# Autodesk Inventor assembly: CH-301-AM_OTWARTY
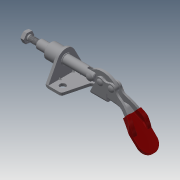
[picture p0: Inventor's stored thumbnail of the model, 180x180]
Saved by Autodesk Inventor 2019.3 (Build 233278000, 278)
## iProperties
Company: Î¢ÈíÖÐ¹ú
Created: 2012-09
Part Number: CH-301-AM_OTWARTY
Material: Ogólny
Description: STEP AP203
Document SubType Name: Assembly
Designer: CADENGINEERING4
Sending System: SolidWorks 2010
Preprocessor: SwSTEP 2.0
Title: CH-301-AM.STEP
Author: Î¢ÈíÓÃ»§
Revision Number: ÈÎºÎ
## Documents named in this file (10)
- D:\Vault_2016\Projekty\STRONA\Push-pull clamp\CH-301-AM\CH-301-AM_OTWARTY.iam
- D:\Vault_2016\Projekty\STRONA\Push-pull clamp\CH-301-AM\CH-SA-042007 SPINDLE SUPPLIED.ipt
- D:\Vault_2016\Projekty\STRONA\Push-pull clamp\CH-301-AM\CH-301-AM-02 CREST STALK.ipt
- D:\Vault_2016\Projekty\STRONA\Push-pull clamp\CH-301-AM\CH-301-AM-05 LEAD SET.ipt
- D:\Vault_2016\Projekty\STRONA\Push-pull clamp\CH-301-AM\CH-301-06.ipt
- D:\Vault_2016\Projekty\STRONA\Push-pull clamp\CH-301-AM\CH-301-AM-03 HANDLE.iam
- D:\Vault_2016\Projekty\STRONA\Push-pull clamp\CH-301-AM\CH-301-07.ipt
- D:\Vault_2016\Projekty\STRONA\Push-pull clamp\CH-301-AM\M4 Nut.ipt
- D:\Vault_2016\Projekty\STRONA\Push-pull clamp\CH-301-AM\CH-301-AM-04 CONNECTING-PLATE.ipt
- D:\Vault_2016\Projekty\STRONA\Push-pull clamp\CH-301-AM\CH-301-AM-01 BASE.ipt
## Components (10 placed, 10 different names)
1. CH-SA-042007 SPINDLE SUPPLIED_1 — Zestawiające:1, Zestawiające:2, Zestawiające:4
2. CH-301-AM-02 CREST STALK_2 — Zestawiające:3, Zestawiające:4, Zestawiające:14, Zestawiające:15, Zestawiające:16
3. CH-301-AM-05 LEAD SET_3 — Zestawiające:15, Zestawiające:17
4. CH-301-06_4 — Zestawiające:5, Zestawiające:8, Równoległe:1, Zestawiające:10
5. CH-301-AM-03 HANDLE_5 [sub-assembly] — Zestawiające:10, Zestawiające:11, Zestawiające:12, Zestawiające:13
6. CH-301-07_6 — Zestawiające:7, Zestawiające:9, Zestawiające:14
7. M4 Nut_7 — Zestawiające:1, Zestawiające:2, Zestawiające:3
8. CH-301-AM-04 CONNECTING-PLATE_8 — Zestawiające:6, Zestawiające:7, Zestawiające:9, Zestawiające:12, Przejściowe:1
9. CH-301-AM-01 BASE_9 — Zestawiające:5, Zestawiające:8, Zestawiające:11, Zestawiające:16, Zestawiające:17, Przejściowe:1
10. CH-301-06_10 — Zestawiające:6, Równoległe:1, Zestawiające:13
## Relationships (19: Mate 17, Flush 1, Transitional 1)
- Zestawiające:1 [Mate]: CH-SA-042007 SPINDLE SUPPLIED_1 ↔ M4 Nut_7
- Zestawiające:2 [Mate]: CH-SA-042007 SPINDLE SUPPLIED_1 ↔ M4 Nut_7
- Zestawiające:3 [Mate]: CH-301-AM-02 CREST STALK_2 ↔ M4 Nut_7
- Zestawiające:4 [Mate]: CH-SA-042007 SPINDLE SUPPLIED_1 ↔ CH-301-AM-02 CREST STALK_2
- Zestawiające:5 [Mate]: CH-301-06_4 ↔ CH-301-AM-01 BASE_9
- Zestawiające:6 [Mate]: CH-301-AM-04 CONNECTING-PLATE_8 ↔ CH-301-06_10
- Zestawiające:7 [Mate]: CH-301-07_6 ↔ CH-301-AM-04 CONNECTING-PLATE_8
- Zestawiające:8 [Mate]: CH-301-06_4 ↔ CH-301-AM-01 BASE_9
- Równoległe:1 [Flush]: CH-301-06_4 ↔ CH-301-06_10
- Zestawiające:9 [Mate]: CH-301-07_6 ↔ CH-301-AM-04 CONNECTING-PLATE_8
- Zestawiające:10 [Mate]: CH-301-06_4 ↔ CH-301-AM-03 HANDLE_5
- Zestawiające:11 [Mate]: CH-301-AM-03 HANDLE_5 ↔ CH-301-AM-01 BASE_9
- Zestawiające:12 [Mate]: CH-301-AM-03 HANDLE_5 ↔ CH-301-AM-04 CONNECTING-PLATE_8
- Zestawiające:13 [Mate]: CH-301-AM-03 HANDLE_5 ↔ CH-301-06_10
- Zestawiające:14 [Mate]: CH-301-AM-02 CREST STALK_2 ↔ CH-301-07_6
- Zestawiające:15 [Mate]: CH-301-AM-02 CREST STALK_2 ↔ CH-301-AM-05 LEAD SET_3
- Zestawiające:16 [Mate]: CH-301-AM-02 CREST STALK_2 ↔ CH-301-AM-01 BASE_9
- Zestawiające:17 [Mate]: CH-301-AM-05 LEAD SET_3 ↔ CH-301-AM-01 BASE_9
- Przejściowe:1 [Transitional]: CH-301-AM-04 CONNECTING-PLATE_8 ↔ CH-301-AM-01 BASE_9
